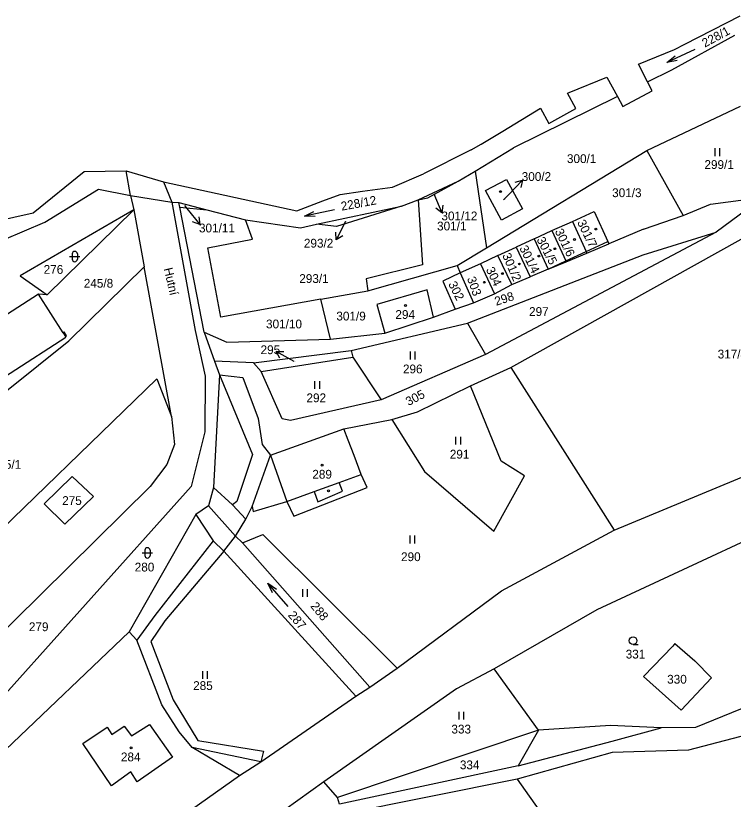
# Model space of a CAD drawing. Extents: x -670359 to -668019, y -978807 to -976674.
# Drawn here: x -669168.2 to -669029.4, y -977081.3 to -976929.7 of the extents above; entities that cross this region are included whole.
import ezdxf

# ---------------------------------------------------------------- set-up
doc = ezdxf.new("R2010")
doc.units = 0
for name, color, linetype in [('Hranice kat_území', 7, 'Continuous'), ('Hranice parcel', 7, 'Continuous'), ('Parcelní čísla', 7, 'Continuous'), ('Pop  PČ popisy', 7, 'Continuous'), ('Vnitřní kresba', 7, 'Continuous'), ('Značky budov', 7, 'Continuous'), ('Značky kultur', 7, 'Continuous')]:
    doc.layers.add(name, color=color, linetype=linetype)

msp = doc.modelspace()

# ---------------------------------------------------------------- linework, layer by layer
at = {"layer": 'Hranice kat_území'}
for p, q in [((-669078.14, -976954.56), (-669073.99, -976952.09)), ((-669080.06, -976955.7), (-669078.14, -976954.56)), ((-669105.41, -976964.3), (-669101.13, -976963.7)), ((-669101.13, -976963.7), (-669095.29, -976962.88)), ((-669108.75, -976965.57), (-669105.41, -976964.3)), ((-669113.78, -976967.49), (-669108.75, -976965.57))]:
    msp.add_line(p, q, dxfattribs=at)
for points in [[(-669038.75, -976935.25), (-669028.05, -976929.74)], [(-669047.75, -976939.13), (-669040.78, -976936.29)], [(-669040.78, -976936.29), (-669038.75, -976935.25)], [(-669045.98, -976942.55), (-669047.75, -976939.13)], [(-669061.14, -976944.57), (-669053.83, -976941.6)], [(-669053.83, -976941.6), (-669051.76, -976945.39)], [(-669045.08, -976944.27), (-669045.98, -976942.55)], [(-669061.46, -976944.75), (-669061.14, -976944.57)], [(-669059.82, -976947.71), (-669061.46, -976944.75)], [(-669051.76, -976945.39), (-669050.73, -976947.28), (-669045.08, -976944.27)], [(-669073.99, -976952.09), (-669066.65, -976947.62)], [(-669066.65, -976947.62), (-669065.07, -976950.57)], [(-669065.07, -976950.57), (-669059.82, -976947.71)], [(-669080.06, -976955.7), (-669089.3, -976960.34)], [(-669164.79, -976967.85), (-669154.91, -976959.88)], [(-669154.91, -976959.88), (-669146.83, -976959.74)], [(-669146.83, -976959.74), (-669139.6, -976961.9)], [(-669095.29, -976962.88), (-669089.3, -976960.34)], [(-669139.6, -976961.9), (-669113.78, -976967.49)], [(-669179.8, -976971.21), (-669164.79, -976967.85)]]:
    msp.add_lwpolyline(points, dxfattribs=at)
at = {"layer": 'Hranice parcel'}
for p, q in [((-669088.47, -976964.97), (-669082.6, -976961.77)), ((-669077.31, -976963.57), (-669073.26, -976961.4)), ((-669073.26, -976961.4), (-669070.17, -976967.12)), ((-669074.22, -976969.3), (-669077.31, -976963.57)), ((-669090.32, -976965.34), (-669088.47, -976964.97)), ((-669136.43, -976966.77), (-669136.6, -976965.89)), ((-669136.6, -976965.89), (-669131.23, -976967.28)), ((-669131.72, -976990.95), (-669136.43, -976966.77)), ((-669136.43, -976966.77), (-669131.23, -976967.28)), ((-669110.02, -976970.08), (-669093.56, -976966.58)), ((-669093.56, -976966.58), (-669106.11, -976970.54)), ((-669131.23, -976967.28), (-669123.73, -976969.22)), ((-669070.17, -976967.12), (-669074.22, -976969.3)), ((-669113.1, -976970.74), (-669110.02, -976970.08)), ((-669106.11, -976970.54), (-669110.02, -976970.08)), ((-669082.82, -976978.06), (-669077.14, -976974.62)), ((-669100.07, -976982.95), (-669082.82, -976978.06)), ((-669082.82, -976978.06), (-669082.2, -976979.48)), ((-669107.3, -976992.29), (-669109.14, -976984.58))]:
    msp.add_line(p, q, dxfattribs=at)
for points in [[(-669041.28, -976940.23), (-669029.12, -976933.54)], [(-669045.98, -976942.55), (-669041.28, -976940.23)], [(-669051.76, -976945.39), (-669071.87, -976955.29)], [(-669046.09, -976955.82), (-669027.97, -976947.26)], [(-669079.31, -976959.81), (-669071.87, -976955.29)], [(-669077.14, -976974.62), (-669046.09, -976955.82)], [(-669046.09, -976955.82), (-669039.09, -976968.4)], [(-669082.6, -976961.77), (-669079.31, -976959.81)], [(-669079.31, -976959.81), (-669077.14, -976974.62)], [(-669090.32, -976965.34), (-669082.6, -976961.77)], [(-669162.56, -976969.69), (-669152.18, -976963.27)], [(-669152.18, -976963.27), (-669145.96, -976964.5)], [(-669072.41, -976997.75), (-669009.84, -976962.88)], [(-669145.96, -976964.5), (-669137.96, -976965.81)], [(-669145.96, -976964.5), (-669145.33, -976967.31)], [(-669093.56, -976966.58), (-669090.32, -976965.34)], [(-669090.32, -976965.34), (-669089.48, -976977.94)], [(-669033.79, -976966.17), (-669023.54, -976964.84)], [(-669023.54, -976964.84), (-669032.72, -976971.59)], [(-669137.96, -976965.81), (-669136.6, -976965.89)], [(-669137.96, -976965.81), (-669133.48, -976990.62)], [(-669039.09, -976968.4), (-669033.79, -976966.17)], [(-669145.33, -976967.31), (-669167.31, -976980.05)], [(-669145.33, -976967.31), (-669162.12, -976983.74)], [(-669145.33, -976967.31), (-669143.32, -976978.29)], [(-669060.51, -976969.52), (-669056.31, -976967.59)], [(-669056.31, -976967.59), (-669053.63, -976973.43)], [(-669046.78, -976971.02), (-669039.09, -976968.4)], [(-669170.44, -976973.02), (-669162.56, -976969.69)], [(-669123.73, -976969.22), (-669113.1, -976970.74)], [(-669122.37, -976972.97), (-669123.73, -976969.22)], [(-669064.46, -976971.31), (-669060.51, -976969.52)], [(-669060.51, -976969.52), (-669057.87, -976975.36)], [(-669067.91, -976972.91), (-669064.46, -976971.31)], [(-669064.46, -976971.31), (-669061.77, -976977.13)], [(-669046.78, -976971.02), (-669053.44, -976973.83)], [(-669131.02, -976974.63), (-669122.37, -976972.97)], [(-669032.72, -976971.59), (-669077.29, -976995.26)], [(-669067.91, -976972.91), (-669071.36, -976974.5)], [(-669067.91, -976972.91), (-669065.19, -976978.79)], [(-669046.8, -976975.98), (-669032.72, -976971.59)], [(-669074.9, -976976.14), (-669071.36, -976974.5)], [(-669071.36, -976974.5), (-669068.69, -976980.27)], [(-669057.73, -976975.65), (-669053.44, -976973.83)], [(-669053.63, -976973.43), (-669053.44, -976973.83)], [(-669128.51, -976988.07), (-669131.02, -976974.63)], [(-669080.79, -976989.17), (-669046.8, -976975.98)], [(-669061.69, -976977.31), (-669057.73, -976975.65)], [(-669057.87, -976975.36), (-669057.73, -976975.65)], [(-669074.9, -976976.14), (-669078.27, -976977.73)], [(-669072.2, -976981.75), (-669074.9, -976976.14)], [(-669065.19, -976978.79), (-669061.69, -976977.31)], [(-669061.77, -976977.13), (-669061.69, -976977.31)], [(-669157.91, -976992.65), (-669143.32, -976978.29)], [(-669138.02, -977007.25), (-669143.32, -976978.29)], [(-669089.48, -976977.94), (-669100.38, -976980.63)], [(-669078.27, -976977.73), (-669082.2, -976979.48)], [(-669078.27, -976977.73), (-669075.6, -976983.5)], [(-669065.19, -976978.79), (-669068.69, -976980.27)], [(-669167.31, -976980.05), (-669162.12, -976983.74)], [(-669082.2, -976979.48), (-669085.57, -976981.07)], [(-669082.2, -976979.48), (-669079.66, -976985.25)], [(-669072.2, -976981.75), (-669068.69, -976980.27)], [(-669100.38, -976980.63), (-669100.07, -976982.95)], [(-669085.57, -976981.07), (-669083.18, -976986.52)], [(-669075.6, -976983.5), (-669072.2, -976981.75)], [(-669163.76, -976983.58), (-669186.19, -976998.05)], [(-669162.12, -976983.74), (-669163.76, -976983.58)], [(-669159.02, -976991.05), (-669163.76, -976983.58)], [(-669109.14, -976984.58), (-669100.07, -976982.95)], [(-669088.62, -976982.74), (-669098.31, -976985.6)], [(-669087.35, -976988.03), (-669088.62, -976982.74)], [(-669079.66, -976985.25), (-669075.6, -976983.5)], [(-669109.14, -976984.58), (-669128.51, -976988.07)], [(-669098.31, -976985.6), (-669096.81, -976991.12)], [(-669087.35, -976988.03), (-669083.18, -976986.52)], [(-669083.18, -976986.52), (-669079.66, -976985.25)], [(-669096.81, -976991.12), (-669087.35, -976988.03)], [(-669103.31, -976994.46), (-669080.79, -976989.17)], [(-669080.79, -976989.17), (-669077.29, -976995.26)], [(-669158.81, -976990.91), (-669159.02, -976991.05)], [(-669158.35, -976991.63), (-669158.81, -976990.91)], [(-669133.48, -976990.62), (-669131.51, -976999.43)], [(-669131.72, -976990.95), (-669127.32, -976992.88)], [(-669131.72, -976990.95), (-669129.74, -976996.55)], [(-669107.3, -976992.29), (-669096.81, -976991.12)], [(-669193.15, -977020.88), (-669157.91, -976992.65)], [(-669190.83, -977012.82), (-669158.45, -976991.93)], [(-669158.56, -976991.77), (-669158.35, -976991.63)], [(-669158.45, -976991.93), (-669158.56, -976991.77)], [(-669127.32, -976992.88), (-669107.3, -976992.29)], [(-669122.21, -976996.89), (-669103.31, -976994.46)], [(-669120.69, -976998.58), (-669102.99, -976995.75)], [(-669103.31, -976994.46), (-669102.99, -976995.75)], [(-669102.99, -976995.75), (-669097.49, -977004)], [(-669077.29, -976995.26), (-669097.49, -977004)], [(-669129.74, -976996.55), (-669128.78, -976999.19)], [(-669122.21, -976996.89), (-669129.74, -976996.55)], [(-669120.69, -976998.58), (-669122.21, -976996.89)], [(-669116.64, -977007.71), (-669120.69, -976998.58)], [(-669080.19, -977001.33), (-669072.41, -976997.75)], [(-669072.41, -976997.75), (-669052.45, -977029.26)], [(-669131.51, -976999.43), (-669131.62, -977010.23)], [(-669128.78, -976999.19), (-669129.9, -977020.95)], [(-669128.78, -976999.19), (-669124.22, -976999.69)], [(-669124.22, -976999.69), (-669121.29, -977007.62)], [(-669090.46, -977006.34), (-669080.19, -977001.33)], [(-669074.31, -977015.91), (-669080.19, -977001.33)], [(-669097.49, -977004), (-669115.04, -977008.03)], [(-669095.42, -977007.85), (-669090.46, -977006.34)], [(-669138.02, -977007.25), (-669137.48, -977012.69)], [(-669121.29, -977007.62), (-669120.5, -977012.66)], [(-669115.04, -977008.03), (-669116.64, -977007.71)], [(-669104.72, -977009.66), (-669095.42, -977007.85)], [(-669095.42, -977007.85), (-669089.13, -977017.87)], [(-669131.62, -977010.23), (-669134.22, -977020.78)], [(-669118.91, -977014.74), (-669104.72, -977009.66)], [(-669103.85, -977011.82), (-669104.72, -977009.66)], [(-669102.73, -977014.79), (-669103.85, -977011.82)], [(-669137.48, -977012.69), (-669138.93, -977016.53)], [(-669120.5, -977012.66), (-669118.91, -977014.74)], [(-669052.45, -977029.26), (-669012.17, -977012.56)], [(-669101.39, -977018.47), (-669102.73, -977014.79)], [(-669138.93, -977016.53), (-669142.15, -977020.76)], [(-669069.76, -977018.72), (-669074.31, -977015.91)], [(-669100.19, -977020.96), (-669101.39, -977018.47)], [(-669089.13, -977017.87), (-669075.72, -977029.42)], [(-669162.66, -977024.14), (-669157.27, -977018.88)], [(-669157.27, -977018.88), (-669153.12, -977022.73)], [(-669075.72, -977029.42), (-669069.76, -977018.72)], [(-669142.15, -977020.76), (-669200.15, -977077.96)], [(-669134.22, -977020.78), (-669175.21, -977066.43)], [(-669129.9, -977020.95), (-669130.87, -977024.55)], [(-669129.9, -977020.95), (-669126.23, -977024.32)], [(-669114.38, -977026.52), (-669100.19, -977020.96)], [(-669153.12, -977022.73), (-669158.67, -977028.07)], [(-669006.72, -977021.8), (-669055.8, -977044.62)], [(-669158.67, -977028.07), (-669162.66, -977024.14)], [(-669130.87, -977024.55), (-669133.36, -977026.22)], [(-669130.87, -977024.55), (-669125.69, -977030.41)], [(-669126.23, -977024.32), (-669123.67, -977027.13)], [(-669122.23, -977025.62), (-669115.73, -977023.71)], [(-669115.73, -977023.71), (-669114.38, -977026.52)], [(-669123.67, -977027.13), (-669122.46, -977024.65)], [(-669122.46, -977024.65), (-669122.23, -977025.62)], [(-669133.36, -977026.22), (-669146.24, -977048.91)], [(-669133.36, -977026.22), (-669130.01, -977031.27)], [(-669125.69, -977030.41), (-669124.33, -977031.69)], [(-669124.33, -977031.69), (-669120.4, -977030.1)], [(-669120.4, -977030.1), (-669094.39, -977055.94)], [(-669074.21, -977040.95), (-669052.45, -977029.26)], [(-669130.01, -977031.27), (-669127.94, -977033.28)], [(-669124.33, -977031.69), (-669099.68, -977059.6)], [(-669127.94, -977033.28), (-669102.41, -977061.35)], [(-669094.39, -977055.94), (-669074.21, -977040.95)], [(-669055.8, -977044.62), (-669075.65, -977056.03)], [(-669146.24, -977048.91), (-669170.18, -977071.73)], [(-669046.75, -977057.51), (-669041.05, -977051.68)], [(-669040.72, -977051.12), (-669041.05, -977051.68)], [(-669040.72, -977051.12), (-669036.81, -977054.49)], [(-669033.62, -977057.78), (-669036.81, -977054.49)], [(-669099.68, -977059.6), (-669094.39, -977055.94)], [(-669075.65, -977056.03), (-669082.91, -977059.89)], [(-669067.09, -977067.91), (-669075.65, -977056.03)], [(-669039.49, -977064.01), (-669046.75, -977057.51)], [(-669033.62, -977057.78), (-669039.49, -977064.01)], [(-669010.88, -977056.89), (-669036.7, -977067.38)], [(-669082.91, -977059.89), (-669108.55, -977077.9)], [(-669102.41, -977061.35), (-669099.68, -977059.6)], [(-669120.79, -977074.02), (-669102.41, -977061.35)], [(-669145.75, -977068.99), (-669142.3, -977066.84)], [(-669142.3, -977066.84), (-669137.84, -977073.1)], [(-669155.2, -977070.49), (-669150.47, -977067.3)], [(-669150.47, -977067.3), (-669149.59, -977068.74)], [(-669149.59, -977068.74), (-669147.19, -977067.15)], [(-669147.19, -977067.15), (-669145.75, -977068.99)], [(-669067.09, -977067.91), (-669105.92, -977080.95)], [(-669067.09, -977067.91), (-669070.99, -977074.8)], [(-669053.11, -977067.01), (-669067.09, -977067.91)], [(-669043.34, -977067.44), (-669053.11, -977067.01)], [(-669036.7, -977067.38), (-669043.34, -977067.44)], [(-669023.97, -977068.13), (-669038.07, -977071.77)], [(-669149.63, -977078.66), (-669155.2, -977070.49)], [(-669052.81, -977072.21), (-669071.17, -977077.39)], [(-669038.07, -977071.77), (-669052.81, -977072.21)], [(-669137.84, -977073.1), (-669144.66, -977077.88)], [(-669124.88, -977076.65), (-669120.79, -977074.02)], [(-669145.94, -977075.95), (-669149.63, -977078.66)], [(-669144.66, -977077.88), (-669145.94, -977075.95)], [(-669070.99, -977074.8), (-669105.55, -977082.22)], [(-669147.03, -977092.35), (-669124.88, -977076.65)], [(-669071.17, -977077.39), (-669105.25, -977084.23)], [(-669071.17, -977077.39), (-669051.32, -977105.5)], [(-669108.55, -977077.9), (-669116.1, -977083.32)], [(-669105.92, -977080.95), (-669108.55, -977077.9)], [(-669105.55, -977082.22), (-669105.92, -977080.95)]]:
    msp.add_lwpolyline(points, dxfattribs=at)
at = {"layer": 'Parcelní čísla'}
for p, q in [((-669071.58, -976961.95), (-669070.14, -976961.52)), ((-669073.82, -976965.38), (-669072.9, -976964.42)), ((-669135.51, -976966.42), (-669135.05, -976967)), ((-669085.57, -976966.36), (-669085.75, -976967.85)), ((-669132.79, -976968.65), (-669132.57, -976970.14)), ((-669104.93, -976972.29), (-669106.18, -976973.11)), ((-669117.06, -976995.99), (-669117.83, -976994.71))]:
    msp.add_line(p, q, dxfattribs=at)
for points in [[(-669072.9, -976964.42), (-669070.14, -976961.52), (-669070.5, -976962.98)], [(-669087.32, -976964.17), (-669085.75, -976967.85), (-669086.95, -976966.95)], [(-669135.05, -976967), (-669132.57, -976970.14), (-669133.96, -976969.58)], [(-669104.38, -976969.54), (-669106.18, -976973.11), (-669106.27, -976971.61)], [(-669114.33, -976996.64), (-669117.83, -976994.71), (-669116.33, -976994.68)]]:
    msp.add_lwpolyline(points, dxfattribs=at)
at = {"layer": 'Vnitřní kresba'}
for points in [[(-669145.96, -976964.5), (-669146.83, -976959.74)], [(-669139.6, -976961.9), (-669137.96, -976965.81)], [(-669057.87, -976975.36), (-669053.63, -976973.43)], [(-669061.77, -976977.13), (-669057.87, -976975.36)], [(-669065.19, -976978.79), (-669061.77, -976977.13)], [(-669159.02, -976991.05), (-669158.56, -976991.77)], [(-669177.34, -977035.3), (-669140.88, -976999.96)], [(-669140.88, -976999.96), (-669138.02, -977007.25)], [(-669128.78, -976999.19), (-669122.35, -977014.57)], [(-669122.35, -977014.57), (-669125.42, -977023.69)], [(-669122.46, -977024.65), (-669118.91, -977014.74)], [(-669118.91, -977014.74), (-669115.73, -977023.71)], [(-669105.6, -977020.01), (-669101.39, -977018.47)], [(-669110.44, -977021.78), (-669105.6, -977020.01)], [(-669105, -977021.66), (-669105.6, -977020.01)], [(-669115.73, -977023.71), (-669110.44, -977021.78)], [(-669110.44, -977021.78), (-669109.73, -977023.73)], [(-669109.73, -977023.73), (-669105, -977021.66)], [(-669125.42, -977023.69), (-669126.23, -977024.32)], [(-669125.69, -977030.41), (-669123.67, -977027.13)], [(-669127.94, -977033.28), (-669125.69, -977030.41)], [(-669130.01, -977031.27), (-669141.27, -977045.72)], [(-669127.94, -977033.28), (-669139.35, -977046.77)], [(-669141.27, -977045.72), (-669144.73, -977050.52)], [(-669139.35, -977046.77), (-669142.01, -977050.76)], [(-669144.73, -977050.52), (-669146.24, -977048.91)], [(-669139.89, -977063.01), (-669144.73, -977050.52)], [(-669142.01, -977050.76), (-669137.72, -977062.06)], [(-669137.72, -977062.06), (-669132.94, -977069.91)], [(-669136.54, -977068.22), (-669139.89, -977063.01)], [(-669134.07, -977071.27), (-669136.54, -977068.22)], [(-669052.8, -977070.05), (-669043.34, -977067.44)], [(-669132.94, -977069.91), (-669120.22, -977071.95)], [(-669124.88, -977076.65), (-669134.07, -977071.27)], [(-669120.79, -977074.02), (-669134.07, -977071.27)], [(-669070.99, -977074.8), (-669052.8, -977070.05)], [(-669120.22, -977071.95), (-669120.79, -977074.02)]]:
    msp.add_lwpolyline(points, dxfattribs=at)
at = {"layer": 'Značky budov'}
for centre in [(-669074.4, -976963.76), (-669055.95, -976971.01), (-669060.09, -976973.01), (-669066.99, -976976.23), (-669063.89, -976974.81), (-669070.77, -976977.76), (-669074.04, -976979.62), (-669077.54, -976981.3), (-669092.78, -976985.78), (-669108.92, -977016.67), (-669145.87, -977071.33)]:
    msp.add_circle(centre, 0.175, dxfattribs=at)
at = {"layer": 'Značky kultur'}
for p, q in [((-669036.8, -976936.26), (-669042.24, -976938.78)), ((-669032.98, -976955.39), (-669032.98, -976956.89)), ((-669031.98, -976956.89), (-669031.98, -976955.39)), ((-669106.49, -976967.26), (-669112.35, -976968.54)), ((-669157.25, -976975.82), (-669157.25, -976976.82)), ((-669156.25, -976975.82), (-669156.25, -976976.82)), ((-669157.75, -976976.32), (-669155.75, -976976.32)), ((-669091.89, -976994.71), (-669091.89, -976996.21)), ((-669090.89, -976996.21), (-669090.89, -976994.71)), ((-669110.37, -977000.43), (-669110.37, -977001.93)), ((-669109.37, -977001.93), (-669109.37, -977000.43)), ((-669083.11, -977011.19), (-669083.11, -977012.69)), ((-669082.11, -977012.69), (-669082.11, -977011.19)), ((-669091.95, -977030.29), (-669091.95, -977031.79)), ((-669090.95, -977031.79), (-669090.95, -977030.29)), ((-669143.69, -977033.62), (-669141.69, -977033.62)), ((-669143.19, -977033.12), (-669143.19, -977034.12)), ((-669142.19, -977033.12), (-669142.19, -977034.12)), ((-669115.46, -977044), (-669119.44, -977039.5)), ((-669112.73, -977040.64), (-669112.73, -977042.14)), ((-669111.73, -977042.14), (-669111.73, -977040.64)), ((-669048.77, -977051.35), (-669047.77, -977051.35)), ((-669132.07, -977056.48), (-669132.07, -977057.98)), ((-669131.07, -977057.98), (-669131.07, -977056.48)), ((-669082.48, -977064.35), (-669082.48, -977065.85)), ((-669081.48, -977065.85), (-669081.48, -977064.35))]:
    msp.add_line(p, q, dxfattribs=at)
for points in [[(-669040.22, -976938.39), (-669042.24, -976938.78), (-669040.64, -976937.48)], [(-669110.29, -976968.6), (-669112.35, -976968.54), (-669110.5, -976967.63)], [(-669118.49, -977041.33), (-669119.44, -977039.5), (-669117.74, -977040.67)]]:
    msp.add_lwpolyline(points, dxfattribs=at)
for centre, radius in [((-669074.4, -976963.76), 0.175), ((-669055.95, -976971.01), 0.175), ((-669060.09, -976973.01), 0.175), ((-669066.99, -976976.23), 0.175), ((-669063.89, -976974.81), 0.175), ((-669070.77, -976977.76), 0.175), ((-669074.04, -976979.62), 0.175), ((-669077.54, -976981.3), 0.175), ((-669092.78, -976985.78), 0.175), ((-669108.92, -977016.67), 0.175), ((-669107.69, -977021.63), 0.175), ((-669048.77, -977050.6), 0.75), ((-669145.87, -977071.33), 0.175)]:
    msp.add_circle(centre, radius, dxfattribs=at)
for centre, start, end in [((-669156.75, -976975.82), 0, 180), ((-669156.75, -976976.82), 180, 0), ((-669142.69, -977033.12), 0, 180), ((-669142.69, -977034.12), 180, 0)]:
    msp.add_arc(centre, 0.5, start, end, dxfattribs=at)

# ---------------------------------------------------------------- texts
at = {"layer": 'Parcelní čísla'}
for s, rotation, p in [('228/1', 28.4006, (-669034.88, -976935.93)), ('228/12', 10.4375, (-669105.12, -976967.46)), ('301/7', 295.9423, (-669059.64, -976969.69)), ('301/6', 295.8253, (-669063.95, -976971.41)), ('301/5', 297.527, (-669067.48, -976973.04)), ('301/4', 296.3814, (-669070.81, -976974.67)), ('301/2', 293.1986, (-669074.11, -976976.07)), ('304', 295.7873, (-669077.28, -976978.83)), ('303', 289.4931, (-669080.91, -976980.54)), ('302', 296.5651, (-669084.56, -976981.62)), ('298', 17.7538, (-669075.24, -976985.85)), ('305', 27.8803, (-669092.2, -977005.25)), ('288', 309.2576, (-669111.26, -977043.97)), ('287', 310.2644, (-669115.61, -977045.73))]:
    msp.add_text(s, height=1.7, rotation=rotation, dxfattribs=at).set_placement(p)
for s, height, p in [('300/1', 1.7, (-669061.56, -976958.24)), ('299/1', 1.7, (-669034.97, -976959.38)), ('300/2', 1.7, (-669070.31, -976961.7)), ('301/3', 1.7, (-669052.82, -976964.83)), ('301/12', 0.1, (-669087.32, -976964.17)), ('300/2', 0.1, (-669073.82, -976965.38)), ('301/11', 0.1, (-669135.51, -976966.42)), ('301/12', 1.7, (-669085.84, -976969.32)), ('301/11', 1.7, (-669132.73, -976971.65)), ('293/2', 0.1, (-669104.37, -976969.52)), ('301/1', 1.7, (-669086.68, -976971.27)), ('293/2', 1.7, (-669112.44, -976974.59)), ('276', 1.7, (-669162.77, -976979.66)), ('245/8', 1.7, (-669155.01, -976982.34)), ('293/1', 1.7, (-669113.33, -976981.43)), ('294', 1.7, (-669094.74, -976988.38)), ('297', 1.7, (-669068.89, -976987.81)), ('301/9', 1.7, (-669106.16, -976988.68)), ('301/10', 1.7, (-669119.76, -976990.21)), ('295', 1.7, (-669120.82, -976995.19)), ('317/4', 1.7, (-669032.41, -976996.03)), ('295', 0.1, (-669114.33, -976996.64)), ('296', 1.7, (-669093.28, -976998.91)), ('292', 1.7, (-669111.94, -977004.49)), ('291', 1.7, (-669084.22, -977015.39)), ('245/1', 1.7, (-669172.8, -977017.37)), ('289', 1.7, (-669110.81, -977019.27)), ('275', 1.7, (-669159.19, -977024.36)), ('290', 1.7, (-669093.65, -977035.22)), ('280', 1.7, (-669145.16, -977037.22)), ('279', 1.7, (-669165.63, -977048.76)), ('331', 1.7, (-669050.2, -977054.05)), ('330', 1.7, (-669042.18, -977058.91)), ('285', 1.7, (-669133.86, -977060.14)), ('333', 1.7, (-669083.91, -977068.55)), ('284', 1.7, (-669147.83, -977073.93)), ('334', 1.7, (-669082.27, -977075.47))]:
    msp.add_text(s, height=height, dxfattribs=at).set_placement(p)
at = {"layer": 'Pop  PČ popisy'}
msp.add_text('Hutní', height=1.7, rotation=283.1232, dxfattribs=at).set_placement((-669139.55, -976978.67))

doc.saveas('drawing.dxf')
